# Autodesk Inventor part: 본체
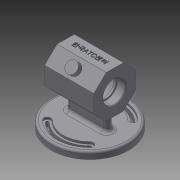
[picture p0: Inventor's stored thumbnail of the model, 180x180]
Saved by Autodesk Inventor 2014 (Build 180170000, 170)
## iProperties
Created: 2017-06
Part Number: 본체
Material: Generic
Document SubType Name: Modeling
Designer: Administrator
Density: 1 g/cm^3
Appearance: Default
Author: Administrator
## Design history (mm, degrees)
sketch "스케치1"
  geometry: C1 r 55 at (0, 0); 1 further point
  constraints: 1 centre point, 1 coincident
  dimensions: "d0" = 110 diameter of C1
extrude "돌출1" new body sketch "스케치1" distance "d1" = 10; taper "d2" = 0 deg
sketch "스케치2"
  geometry: L1 (0, 0)-(-33.941, 33.941); L2 (0, 0)-(48, 0); L3 (0, 0)-(33.941, 33.941); L4 (0, 0)-(48, 0); L5 (0, 0)-(-33.941, -33.941); L6 (0, 0)-(48, 0); L7 (0, 0)-(33.941, -33.941); L8 (0, 0)-(48, 0); C1 r 5 at (30.406, 30.406); C2 r 5 at (-30.406, -30.406); C3 r 5 at (30.406, -30.406); A1 r 38 centre (0, 0) between (-26.87, -26.87) and (26.87, -26.87); A2 r 38 centre (0, 0) between (26.87, 26.87) and (-26.87, 26.87); A3 r 48 centre (0, 0) between (-33.941, -33.941) and (33.941, -33.941); A4 r 48 centre (0, 0) between (33.941, 33.941) and (-33.941, 33.941); A5 r 5 centre (-30.406, 30.406) between (-33.941, 33.941) and (-26.87, 26.87)
  constraints: 16 end point, 10 point on circle, 8 centre point, 4 equal length, 4 horizontal, 4 point on line, 1 coincident
  dimensions: "d6" = 135 deg angle of L2 L1; "d7" = 45 deg angle of L4 L3; "d8" = 135 deg angle of L5 L6; "d9" = 45 deg angle of L7 L8; "d10" = 10 diameter of A5; "d11" = 10 diameter of C1; "d12" = 10 diameter of C2; "d13" = 10 diameter of C3
extrude "돌출2" cut sketch "스케치2" distance "d14" = 3; taper "d15" = 0 deg
sketch "스케치3"
  geometry: C1 r 55 at (0, 0) reference; A1 r 5 centre (-30.406, -30.406) between (-26.87, -26.87) and (-33.941, -33.941) reference; A2 r 5 centre (30.406, -30.406) between (33.941, -33.941) and (26.87, -26.87) reference; A3 r 5 centre (30.406, 30.406) between (26.87, 26.87) and (33.941, 33.941) reference; A4 r 5 centre (-30.406, 30.406) between (-33.941, 33.941) and (-26.87, 26.87) reference; A5 r 2 centre (-30.406, 30.406) between (-31.82, 31.82) and (-28.991, 28.991); A6 r 2 centre (30.406, 30.406) between (28.991, 28.991) and (31.82, 31.82); A7 r 2 centre (-30.406, -30.406) between (-28.991, -28.991) and (-31.82, -31.82); A8 r 41 centre (0, 0) between (-28.991, -28.991) and (28.991, -28.991); A9 r 41 centre (0, 0) between (28.991, 28.991) and (-28.991, 28.991); A10 r 45 centre (0, 0) between (-31.82, -31.82) and (31.82, -31.82); A11 r 45 centre (0, 0) between (31.82, 31.82) and (-31.82, 31.82); A12 r 2 centre (30.406, -30.406) between (28.991, -28.991) and (31.82, -31.82)
  constraints: 16 point on circle, 8 centre point, 6 coincident
  dimensions: "d16" = 4 diameter of A5; "d17" = 4 diameter of A6; "d18" = 4 diameter of A7; "d21" = 4 diameter of A12
extrude "돌출3" cut sketch "스케치3" stored distance "d22" = 3; taper "d23" = 0 deg
sketch "스케치4"
  geometry: L1 (24, 5)-(-24, 5); L2 (-24, 5)-(-24, -5); L3 (-24, -5)-(24, -5); L4 (24, -5)-(24, 5); L5 (24, 5)-(-24, -5); L6 (-24, 5)-(24, -5); C1 r 55 at (0, 0) reference; C2 r 5 at (-24, 0); C3 r 5 at (24, 0)
  constraints: 12 end point, 4 midpoint, 2 centre point, 2 parallel, 1 horizontal, 1 perpendicular
  dimensions: "d24" = 48 distance between parallel lines of L4 L2; "d25" = 10 distance between parallel lines of L3 L1; "d26" = 10 diameter of C2; "d27" = 10 diameter of C3
extrude "돌출4" join sketch "스케치4" distance "d28" = 52; taper "d29" = 0 deg
node "작업 평면1"
sketch "스케치5"
  geometry: L1 (38, 10)-(38, 7) reference; L2 (38, 7)-(41, 7) reference; L3 (41, 7)-(41, 0) reference; L4 (41, 0)-(-41, 0) reference; L5 (-41, 0)-(-41, 7) reference; L6 (-41, 7)-(-38, 7) reference; L7 (-38, 7)-(-38, 10) reference; L8 (-38, 10)-(-5, 10) reference; L9 (-5, 10)-(-5, 62) reference; L10 (-5, 62)-(5, 62) reference; L11 (5, 62)-(5, 10) reference; L12 (5, 10)-(38, 10) reference; L13 (-55, 0)-(-55, 10) reference; L14 (-55, 10)-(-48, 10) reference; L15 (-48, 10)-(-48, 7) reference; L16 (-48, 7)-(-45, 7) reference; L17 (-45, 7)-(-45, 0) reference; L18 (-45, 0)-(-55, 0) reference; L19 (55, 10)-(55, 0) reference; L20 (55, 0)-(45, 0) reference; L21 (45, 0)-(45, 7) reference; L22 (45, 7)-(48, 7) reference; L23 (48, 7)-(48, 10) reference; L24 (48, 10)-(55, 10) reference; L25 (-11.904, 92)-(12.795, 91.631); L26 (12.795, 91.631)-(30, 73.904); L27 (30, 73.904)-(29.631, 49.205); L28 (29.631, 49.205)-(11.904, 32); L29 (11.904, 32)-(-12.795, 32.369); L30 (-12.795, 32.369)-(-30, 50.096); L31 (-30, 50.096)-(-29.631, 74.795); L32 (-29.631, 74.795)-(-11.904, 92); 2 further points
  constraints: 16 end point, 17 other
extrude "돌출5" join sketch "스케치5" stored distance "d32" = 70; taper "d33" = 0 deg
node "작업 평면2"
sketch "스케치6"
  geometry: L1 (38, 10)-(38, 7) reference; L2 (38, 7)-(41, 7) reference; L3 (41, 7)-(41, 0) reference; L4 (41, 0)-(-41, 0) reference; L5 (-41, 0)-(-41, 7) reference; L6 (-41, 7)-(-38, 7) reference; L7 (-38, 7)-(-38, 10) reference; L8 (-38, 10)-(-5, 10) reference; L9 (-5, 10)-(-5, 32.253) reference; L10 (-5, 32.253)-(-12.795, 32.369) reference; L11 (-12.795, 32.369)-(-30, 50.096) reference; L12 (-30, 50.096)-(-29.631, 74.795) reference; L13 (-29.631, 74.795)-(-11.904, 92) reference; L14 (-11.904, 92)-(12.795, 91.631) reference; L15 (12.795, 91.631)-(30, 73.904) reference; L16 (30, 73.904)-(29.631, 49.205) reference; L17 (29.631, 49.205)-(11.904, 32) reference; L18 (11.904, 32)-(5, 32.103) reference; L19 (5, 32.103)-(5, 10) reference; L20 (5, 10)-(38, 10) reference; L21 (-55, 0)-(-55, 10) reference; L22 (-55, 10)-(-48, 10) reference; L23 (-48, 10)-(-48, 7) reference; L24 (-48, 7)-(-45, 7) reference; L25 (-45, 7)-(-45, 0) reference; L26 (-45, 0)-(-55, 0) reference; L27 (55, 10)-(55, 0) reference; L28 (55, 0)-(45, 0) reference; L29 (45, 0)-(45, 7) reference; L30 (45, 7)-(48, 7) reference; L31 (48, 7)-(48, 10) reference; L32 (48, 10)-(55, 10) reference; L33 (-29.815, 62.445)-(29.815, 61.555); L34 (0, 62)-(0, 91.822); L35 (0, 62)-(-26.038, 88.038); L36 (-26.829, 77.515)-(-21.087, 83.087); L37 (-31.779, 82.465)-(-26.038, 88.038); L38 (-5.657, 56.343)-(-31.779, 82.465); L39 (-5.657, 56.343)-(0, 62); 1 further point
  constraints: 14 end point, 4 point on line, 3 midpoint, 2 parallel, 2 perpendicular, 1 collinear
  dimensions: "d35" = 45 deg angle of L34 L35; "d36" = 7 distance between parallel lines of L13 L37; "d37" = 8 distance between parallel lines of L35 L38
revolve "회전1" sketch "스케치6" stored, may be unused: angle "d38" = 90 deg
node "작업 평면3"
sketch "스케치7"
  geometry: L1 (-55, 0)-(-55, 10) reference; L2 (-55, 10)-(-29, 10) reference; L3 (-29, 10)-(-29, 32.178) reference; L4 (-29, 32.178)-(-35, 32.178) reference; L5 (-35, 32.178)-(-35, 91.822) reference; L6 (-35, 91.822)-(35, 91.822) reference; L7 (35, 91.822)-(35, 32.178) reference; L8 (35, 32.178)-(29, 32.178) reference; L9 (29, 32.178)-(29, 10) reference; L10 (29, 10)-(55, 10) reference; L11 (55, 10)-(55, 0) reference; L12 (55, 0)-(-55, 0) reference; L13 (-35, 62)-(35, 62); L14 (35, 78)-(23, 78); L15 (23, 78)-(23, 62); L16 (23, 76)-(20, 76); L17 (20, 76)-(20, 62); L18 (20, 76)-(20, 87); L19 (20, 87)-(-20, 87); L20 (-20, 87)-(-20, 62); L21 (-20, 76)-(-23, 76); L22 (-23, 76)-(-23, 62); L23 (-23, 76)-(-23, 78); L24 (-23, 78)-(-35, 78); L25 (20, 76)-(20, 87); L26 (-23, 76)-(-23, 78); 1 further point
  constraints: 28 end point, 8 perpendicular, 8 point on line, 3 collinear, 2 midpoint, 2 parallel
  dimensions: "d40" = 32 diameter of L14 L13; "d41" = 32 diameter of L24 L13; "d42" = 28 diameter of L16 L13; "d43" = 28 diameter of L21 L13; "d44" = 12 distance between parallel lines of L7 L15; "d45" = 12 distance between parallel lines of L22 L5; "d46" = 3 distance between parallel lines of L20 L22; "d47" = 3 distance between parallel lines of L15 L17; "d48" = 50 diameter of L19 L13
revolve "회전2" sketch "스케치7" stored, may be unused: angle "d49" = 90 deg
sketch "스케치8"
  geometry: L1 (70, 42.17)-(0, 42.17) reference; 2 further points
  constraints: 1 other
  dimensions: "d52" = 35 horizontal distance of point (35, 12.17) L1.end; "d53" = 30 distance from line of point (35, 12.17) L1
feature "엠보싱1" sketch "스케치8" dims "d54" = 0.5, "d55" = 0
fillet "모깎기1" dims "d56" = 3
fillet "모깎기2" dims "d57" = 5
chamfer "모따기1" distance "d58" = 1; stored, may be unused: second distance "d59" = 2, angle "d60" = 45 deg
fillet "모깎기3" dims "d61" = 3
fillet "모깎기4" dims "d62" = 0.3
node "작업 평면4"
node "작업 평면5"
node "솔리드1"
node "절단 모서리 투영1"
node "절단 모서리 투영2"
node "절단 모서리 투영3"
other parameters: "d3" = 86, "d4" = 96, "d5" = 76, "d20" = 82, "d30" = 0, "d34" = 0, "d39" = 0, "d72" = 7, "d80" = 7
